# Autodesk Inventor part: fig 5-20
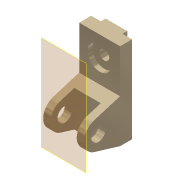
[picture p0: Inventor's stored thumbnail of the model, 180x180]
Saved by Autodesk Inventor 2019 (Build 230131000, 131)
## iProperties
Shininess: 65.0
Angle Display Precision: 2
Document Length Units: 11269
Document Angle Units: 11279
Document Time Units: 11290
Document Mass Units: 11283
Document Length Units Precision: 3
Document Angle Units Precision: 2
Compacted: False
Created: 2001-11
Part Number: fig 5-20
Document SubType Name: Modeling
Designer: Renu Muthoo
Density: 1 g/cm^3
Material: Generic
Appearance: Metal-Titanium (Polished)
Density: 0.0
Volumn: 0.0
Area: 0.0
PropertySet Name: Model Information
Control State: 0
Master: False
Checked Out: False
Author: Renu Muthoo
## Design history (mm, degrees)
node "Sketch1"
sketch "Sketch2"
  geometry: L1 (33.257, 104.664)-(33.257, -75.336); L2 (33.257, -75.336)-(8.257, -75.336); L3 (8.257, -75.336)-(-45.451, -59.045); L4 (-45.451, -1.628)-(8.257, 14.664); L5 (8.257, 14.664)-(8.257, 104.664); L6 (8.257, 104.664)-(33.257, 104.664); C1 r 15 at (-36.743, -30.336); A1 r 30 centre (-36.743, -30.336) between (-45.451, -1.628) and (-45.451, -59.045)
  constraints: 12 end point, 2 centre point, 2 equal length, 2 parallel, 2 point on circle, 2 tangent, 1 coincident, 1 perpendicular, 1 vertical
  dimensions: "d0" = 180 distance of L1.start L1.end; "d1" = 30 radius of A1; "d2" = 25 distance of L5.end L1.start; "d3" = 45 distance from line of L2 A1.centre; "d4" = 70 distance from line of L1 A1.centre; "d5" = 30 diameter of C1
extrude "Extrusion1" new body sketch "Sketch2" distance "d6" = 85; taper "d7" = 0 deg
workplane "Work Plane1"
sketch "Sketch3"
  geometry: L1 (15, 62.364)-(70, 62.364); L2 (70, 62.364)-(70, -52.386); L3 (70, -52.386)-(15, -52.386); L4 (15, -52.386)-(15, 62.364); L5 (0, -45)-(0, -28.708) reference
  constraints: 8 end point, 2 parallel, 1 horizontal, 1 perpendicular
  dimensions: "d8" = 55 distance of L1.start L1.end; "d9" = 15 distance between parallel lines of L5 L4
extrude "Extrusion2" cut sketch "Sketch3" distance "d10" = 50; taper "d11" = 0 deg
sketch "Sketch4"
  geometry: L1 (0, 25)-(85, 25) reference; L2 (0, 0)-(0, 25) reference; L3 (20, 25)-(65, 25); L4 (65, 25)-(65, 35); L5 (65, 35)-(20, 35); L6 (20, 35)-(20, 25)
  constraints: 8 end point, 2 parallel, 1 horizontal, 1 perpendicular, 1 point on line
  dimensions: "d12" = 45 distance of L4.end L5.end; "d13" = 10 distance of L3.end L4.end; "d14" = 20 distance between parallel lines of L2 L6
extrude "Extrusion3" join sketch "Sketch4" stored distance "d15" = 50; taper "d16" = 0 deg
sketch "Sketch5"
  geometry: L1 (85, 0)-(85, 90) reference; L2 (0, 90)-(85, 90) reference; 1 further point
  dimensions: "d17" = 42 distance from line of L2 point (42.5, 48); "d18" = 42.5 distance from line of L1 point (42.5, 48)
hole "Hole1" sketch "Sketch5" at (42.5, 48) diameter "d19" = 20; stored, may be unused: countersink angle "d23" = 82 deg, drill point angle "d25" = 118 deg; dims "d20" = 6, "d21" = 50, "d22" = 10, "d24" = 8
workplane "Work Plane10"
body "Solid1"
